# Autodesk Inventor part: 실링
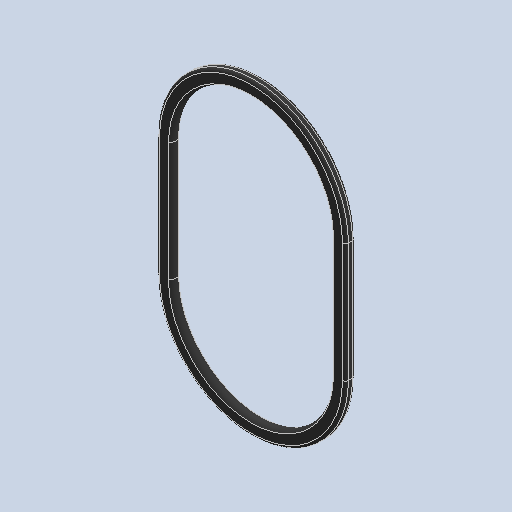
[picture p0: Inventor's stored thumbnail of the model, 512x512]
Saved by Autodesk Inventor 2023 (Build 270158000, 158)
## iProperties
Created: 2025-10
Part Number: 실링
Material: 고무
Document SubType Name: Modeling
Designer: home
Density: 0.93 g/cm^3
Appearance: 기본값
Author: jhkim
Sending System: Autodesk Inventor 2026
Preprocessor: ST-DEVELOPER v20.1
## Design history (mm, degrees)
feature "솔리드3"
node "솔리드1"
